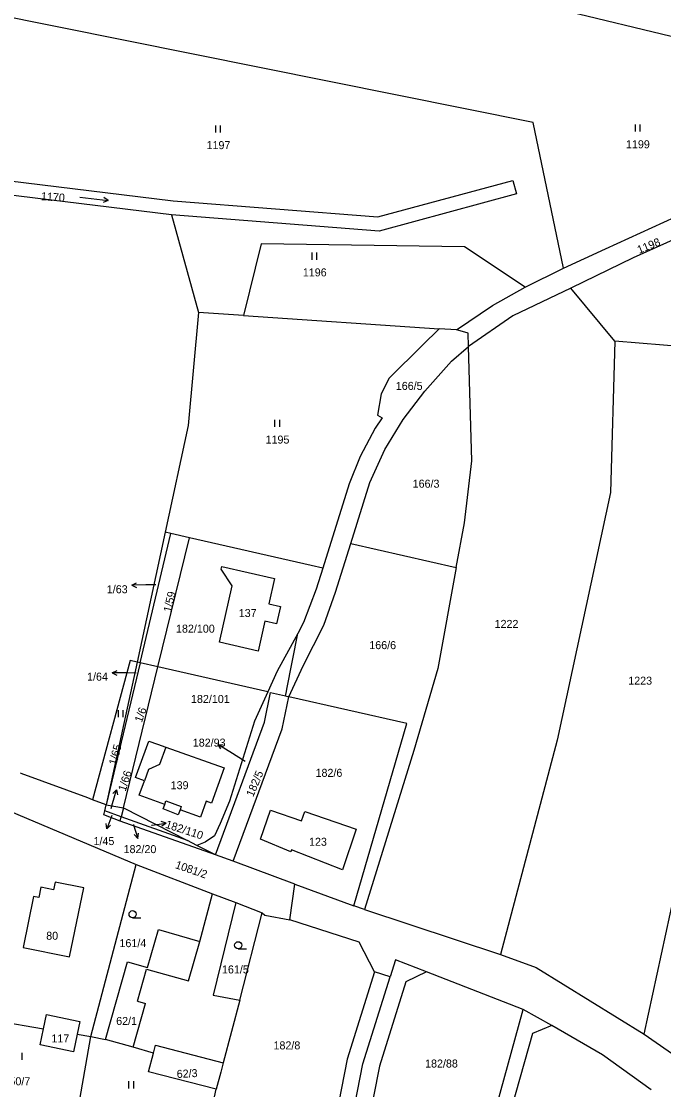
# Model space of a CAD drawing. Extents: x -746176 to -739709, y -1127410 to -1124482.
# Drawn here: x -742011.1 to -741874.7, y -1126433.2 to -1126206.3 of the extents above; entities that cross this region are included whole.
import ezdxf

# ---------------------------------------------------------------- set-up
doc = ezdxf.new("R2010")
doc.units = 0
for name, color, linetype in [('Hranice parcel', 7, 'Continuous'), ('Parcelní čísla', 7, 'Continuous'), ('Pop  PČ popisy', 7, 'Continuous'), ('Vnitřní kresba', 7, 'Continuous'), ('Značky kultur', 7, 'Continuous')]:
    doc.layers.add(name, color=color, linetype=linetype)

msp = doc.modelspace()

# ---------------------------------------------------------------- linework, layer by layer
at = {"layer": 'Hranice parcel'}
for p, q in [((-741979.16, -1126247.44), (-741973.49, -1126268.18)), ((-741904.1, -1126262.78), (-741895.95, -1126258.73)), ((-741885.09, -1126274.27), (-741894.45, -1126263.02)), ((-741963.91, -1126268.84), (-741973.49, -1126268.18)), ((-741963.91, -1126268.84), (-741922.39, -1126271.67)), ((-741918.69, -1126271.87), (-741922.39, -1126271.67)), ((-741856.86, -1126276.54), (-741885.09, -1126274.27)), ((-741980.55, -1126314.84), (-741986.51, -1126342.46)), ((-741985.86, -1126342.61), (-741979.32, -1126315.12)), ((-741982.09, -1126343.47), (-741975.4, -1126316.01)), ((-741979.32, -1126315.12), (-741980.55, -1126314.84)), ((-741975.4, -1126316.01), (-741979.32, -1126315.12)), ((-741941.15, -1126317.27), (-741918.74, -1126322.36)), ((-741951.16, -1126334.05), (-741952.39, -1126336.34)), ((-741952.39, -1126336.34), (-741956.73, -1126344.37)), ((-741986.51, -1126342.46), (-741993.03, -1126372.73)), ((-741985.86, -1126342.61), (-741993.03, -1126372.73)), ((-741989.38, -1126373.38), (-741982.09, -1126343.47)), ((-741985.86, -1126342.61), (-741986.51, -1126342.46)), ((-741982.09, -1126343.47), (-741985.86, -1126342.61)), ((-741958.73, -1126348.77), (-741982.09, -1126343.47)), ((-741954.27, -1126349.79), (-741951.24, -1126343.21)), ((-741956.73, -1126344.37), (-741958.73, -1126348.77)), ((-741955, -1126349.62), (-741954.27, -1126349.79)), ((-741993.03, -1126372.73), (-741995.94, -1126371.66)), ((-741993.33, -1126374), (-741993.03, -1126372.73)), ((-741993.03, -1126372.73), (-741989.38, -1126373.38)), ((-741989.85, -1126375.26), (-741993.33, -1126374)), ((-741990.09, -1126376.24), (-741989.85, -1126375.26)), ((-741989.38, -1126373.38), (-741989.85, -1126375.26)), ((-741975.79, -1126380.32), (-741989.85, -1126375.26)), ((-741989.38, -1126373.38), (-741975.79, -1126380.32)), ((-741969.88, -1126383.35), (-741990.09, -1126376.24)), ((-741973.78, -1126381.35), (-741975.79, -1126380.32)), ((-741972.03, -1126380.69), (-741973.78, -1126381.35)), ((-741969.88, -1126383.35), (-741973.78, -1126381.35)), ((-741966.13, -1126384.73), (-741969.88, -1126383.35)), ((-741996.32, -1126421.94), (-741986.71, -1126385.43)), ((-741986.71, -1126385.43), (-741970.45, -1126391.64)), ((-741953, -1126389.58), (-741966.13, -1126384.73)), ((-741954.07, -1126397.17), (-741953, -1126389.58)), ((-741953, -1126389.58), (-741940.51, -1126394.18)), ((-741970.45, -1126391.64), (-741965.53, -1126393.52)), ((-741965.53, -1126393.52), (-741959.96, -1126395.65)), ((-741964.66, -1126414.2), (-741959.96, -1126395.65)), ((-741938.23, -1126394.97), (-741940.51, -1126394.18)), ((-741938.23, -1126394.97), (-741909.32, -1126404.54)), ((-741932.77, -1126409.29), (-741936.11, -1126408.24)), ((-741904.57, -1126416.23), (-741925.07, -1126408.25)), ((-741964.66, -1126414.2), (-741968.2, -1126427.52)), ((-741898.42, -1126419.6), (-741904.57, -1126416.23)), ((-741999.2, -1126421.47), (-741996.32, -1126421.94)), ((-741999.11, -1126438.17), (-741996.32, -1126421.94)), ((-741996.32, -1126421.94), (-741993.21, -1126422.56)), ((-741878.88, -1126421.46), (-741852.49, -1126439.8)), ((-741971.96, -1126443.41), (-741969.67, -1126433.17))]:
    msp.add_line(p, q, dxfattribs=at)
for points in [[(-741895.95, -1126258.73), (-741902.39, -1126227.83), (-742032.39, -1126201.61)], [(-741748.2, -1126234.56), (-741750.5, -1126234.41), (-741798.02, -1126225.94), (-741818.62, -1126222.33), (-741833.76, -1126219.08), (-741900.7, -1126202.92)], [(-741979.16, -1126247.44), (-742018.02, -1126242.67), (-742051.56, -1126236.78), (-742071.8, -1126233.98)], [(-742037.23, -1126236.37), (-742017.58, -1126239.71), (-741978.86, -1126244.46), (-741935.37, -1126247.86), (-741906.75, -1126240.11), (-741905.97, -1126243.01), (-741935.09, -1126250.9), (-741979.16, -1126247.44)], [(-741895.95, -1126258.73), (-741887.06, -1126254.64), (-741867.23, -1126245.63), (-741859.7, -1126242.83), (-741853.68, -1126241.82), (-741840.1, -1126242.23)], [(-741841.74, -1126251.46), (-741852.27, -1126246.05), (-741856.49, -1126246.25), (-741862.01, -1126247.91), (-741881.16, -1126256.56), (-741894.45, -1126263.02)], [(-741904.1, -1126262.78), (-741917.02, -1126254.2), (-741960.14, -1126253.61), (-741963.91, -1126268.84)], [(-741918.69, -1126271.87), (-741911.03, -1126266.72), (-741904.1, -1126262.78)], [(-741894.45, -1126263.02), (-741906.75, -1126268.89), (-741916.15, -1126275.4)], [(-741973.49, -1126268.18), (-741975.66, -1126292.15), (-741980.55, -1126314.84)], [(-741922.39, -1126271.67), (-741925.91, -1126275.15), (-741932.95, -1126282.11), (-741934.69, -1126285.47), (-741935.47, -1126289.95), (-741934.45, -1126290.55), (-741935.93, -1126292.73), (-741939.16, -1126298.76), (-741941.48, -1126304.55), (-741947.05, -1126322.45)], [(-741916.15, -1126275.4), (-741916.23, -1126272.57), (-741918.37, -1126271.96), (-741918.69, -1126271.87)], [(-741941.15, -1126317.27), (-741937.11, -1126304.31), (-741933.93, -1126297.28), (-741929.99, -1126290.94), (-741925.39, -1126284.87), (-741919.74, -1126278.55), (-741916.15, -1126275.4)], [(-741918.74, -1126322.36), (-741917, -1126312.88), (-741915.44, -1126299.69), (-741916.15, -1126275.4)], [(-741885.09, -1126274.27), (-741886, -1126306.44), (-741897.34, -1126359), (-741909.32, -1126404.54)], [(-741878.88, -1126421.46), (-741868.71, -1126374.72), (-741857.4, -1126314.53), (-741856.86, -1126276.54)], [(-741947.05, -1126322.45), (-741949.55, -1126321.88), (-741975.4, -1126316.01)], [(-741951.24, -1126343.21), (-741946.82, -1126334.61), (-741944.36, -1126327.59), (-741941.15, -1126317.27)], [(-741969.03, -1126338.22), (-741966.34, -1126326.2), (-741968.61, -1126322.66), (-741968.49, -1126322.14), (-741957.3, -1126324.7), (-741958.52, -1126330.09), (-741956.07, -1126330.63), (-741956.89, -1126334.27), (-741959.34, -1126333.71), (-741960.77, -1126340.08), (-741969.03, -1126338.22)], [(-741947.05, -1126322.45), (-741948.46, -1126326.96), (-741951.16, -1126334.05)], [(-741918.74, -1126322.36), (-741922.66, -1126343.77), (-741927.73, -1126361.18), (-741938.23, -1126394.97)], [(-741955, -1126349.62), (-741954.81, -1126348.66), (-741954.71, -1126348.16), (-741952.39, -1126336.34)], [(-741986.51, -1126342.46), (-741987.96, -1126342.12), (-741995.94, -1126371.66)], [(-741958.73, -1126348.77), (-741961.57, -1126355.01), (-741966.88, -1126371.94), (-741968.84, -1126376.73), (-741970.09, -1126379.3), (-741972.03, -1126380.69)], [(-741969.88, -1126383.35), (-741959.42, -1126355.18), (-741958.17, -1126348.9), (-741955, -1126349.62)], [(-741966.13, -1126384.73), (-741955.67, -1126356.57), (-741954.27, -1126349.79)], [(-741940.51, -1126394.18), (-741929.25, -1126355.48), (-741954.27, -1126349.79)], [(-741977.77, -1126374.86), (-741980.95, -1126373.62), (-741980.61, -1126372.64), (-741986.02, -1126370.7), (-741984.92, -1126367.63), (-741986.82, -1126366.94), (-741984.02, -1126359.21), (-741982.15, -1126359.85), (-741980.39, -1126360.49), (-741968.02, -1126364.9), (-741970.7, -1126372.41), (-741971.84, -1126372), (-741973.03, -1126375.35), (-741977.37, -1126373.8), (-741977.77, -1126374.86)], [(-741995.94, -1126371.66), (-741996.93, -1126371.29), (-742011.08, -1126366.08), (-742011.25, -1126365.95)], [(-742017.65, -1126371.11), (-742017.02, -1126371.6), (-742014.99, -1126373.44), (-741986.71, -1126385.43)], [(-741990.09, -1126376.24), (-741993.53, -1126374.84), (-741993.33, -1126374)], [(-741958.18, -1126373.85), (-741951.58, -1126376.12), (-741950.91, -1126374.18), (-741939.97, -1126377.94), (-741942.91, -1126386.52), (-741953.71, -1126382.33), (-741953.86, -1126382.76), (-741960.32, -1126380.06), (-741958.18, -1126373.85)], [(-742003.87, -1126389.15), (-742004.21, -1126390.8), (-742006.94, -1126390.24), (-742007.38, -1126392.41), (-742008.47, -1126392.19), (-742010.7, -1126403.03), (-742000.83, -1126405.05), (-741997.82, -1126390.4), (-742003.87, -1126389.15)], [(-741993.21, -1126422.56), (-741988.52, -1126406.06), (-741984.26, -1126407.27), (-741981.98, -1126399.24), (-741973.18, -1126401.74), (-741970.45, -1126391.64)], [(-741965.53, -1126393.52), (-741970.31, -1126413.16), (-741964.66, -1126414.2)], [(-741959.96, -1126395.65), (-741959.39, -1126396.19), (-741954.07, -1126397.17)], [(-741936.11, -1126408.24), (-741939.36, -1126401.91), (-741954.07, -1126397.17)], [(-741909.32, -1126404.54), (-741901.76, -1126407.3), (-741878.88, -1126421.46)], [(-741925.07, -1126408.25), (-741931.64, -1126405.69), (-741932.77, -1126409.29)], [(-741954.32, -1126508.73), (-741938.56, -1126427.78), (-741932.77, -1126409.29)], [(-741936.11, -1126408.24), (-741941.9, -1126426.74), (-741946.15, -1126448.52)], [(-741925.07, -1126408.25), (-741929.41, -1126410.36), (-741935.06, -1126428.26), (-741937.58, -1126441.15)], [(-742024.68, -1126414.24), (-742015.91, -1126416.77), (-742016.26, -1126418.65), (-742006.36, -1126420.29)], [(-742006.36, -1126420.29), (-742005.72, -1126417.27), (-741998.63, -1126418.76), (-741999.2, -1126421.47)], [(-741912.45, -1126446.2), (-741911.72, -1126442.48), (-741904.57, -1126416.23)], [(-741999.2, -1126421.47), (-741999.99, -1126425.22), (-742007.08, -1126423.73), (-742006.36, -1126420.29)], [(-741898.42, -1126419.6), (-741902.57, -1126421.34), (-741908.84, -1126443.59), (-741914.46, -1126471.66), (-741921.58, -1126508.41), (-741929.05, -1126550.68), (-741935.86, -1126591.95), (-741938.82, -1126591.67)], [(-741877.38, -1126433.3), (-741887.7, -1126425.84), (-741898.42, -1126419.6)], [(-741983.01, -1126425.46), (-741987.35, -1126424.23), (-741993.21, -1126422.56)], [(-741983.01, -1126425.46), (-741982.58, -1126423.8), (-741968.2, -1126427.52)], [(-741969.67, -1126433.17), (-741984.04, -1126429.45), (-741983.01, -1126425.46)], [(-741968.2, -1126427.52), (-741968.72, -1126429.53), (-741969.67, -1126433.17)]]:
    msp.add_lwpolyline(points, dxfattribs=at)
at = {"layer": 'Pop  PČ popisy'}
for p, q in [((-741987.601, -1126326.082), (-741986.608, -1126325.564)), ((-741984.6, -1126326.03), (-741987.601, -1126326.082)), ((-741987.601, -1126326.082), (-741986.59, -1126326.566)), ((-741982.49, -1126326), (-741984.6, -1126326.03)), ((-741991.751, -1126344.678), (-741990.74, -1126344.194)), ((-741988.75, -1126344.73), (-741991.751, -1126344.678)), ((-741991.751, -1126344.678), (-741990.758, -1126345.196)), ((-741986.71, -1126344.75), (-741988.75, -1126344.73)), ((-741966.82, -1126361.51), (-741969.365, -1126359.92)), ((-741969.365, -1126359.92), (-741968.25, -1126360.026)), ((-741969.365, -1126359.92), (-741968.781, -1126360.875)), ((-741963.58, -1126363.54), (-741966.82, -1126361.51)), ((-741991.68, -1126372.43), (-741990.853, -1126369.545)), ((-741990.853, -1126369.545), (-741991.61, -1126370.37)), ((-741990.853, -1126369.545), (-741990.648, -1126370.646)), ((-741991.98, -1126373.5), (-741991.68, -1126372.43)), ((-741991.82, -1126375.03), (-741992.944, -1126377.812)), ((-741992.944, -1126377.812), (-741993.033, -1126376.696)), ((-741992.944, -1126377.812), (-741992.105, -1126377.072)), ((-741987.25, -1126376.89), (-741987.22, -1126377)), ((-741987.22, -1126377), (-741986.343, -1126379.87)), ((-741983.4, -1126377.04), (-741983.31, -1126377.03)), ((-741983.31, -1126377.03), (-741980.331, -1126376.664)), ((-741980.331, -1126376.664), (-741981.386, -1126376.289)), ((-741980.331, -1126376.664), (-741981.264, -1126377.283)), ((-741986.343, -1126379.87), (-741987.114, -1126379.059)), ((-741986.343, -1126379.87), (-741986.157, -1126378.766))]:
    msp.add_line(p, q, dxfattribs=at)
at = {"layer": 'Vnitřní kresba'}
for p, q in [((-741980.39, -1126360.49), (-741981.73, -1126364.15)), ((-741984.06, -1126365.24), (-741984.92, -1126367.63)), ((-741981.73, -1126364.15), (-741984.06, -1126365.24)), ((-741980.61, -1126372.64), (-741980.36, -1126371.92)), ((-741980.36, -1126371.92), (-741977.1, -1126373.07)), ((-741977.1, -1126373.07), (-741977.37, -1126373.8)), ((-741975.58, -1126410.16), (-741973.18, -1126401.74)), ((-741986.43, -1126414.45), (-741984.48, -1126407.62)), ((-741984.48, -1126407.62), (-741975.58, -1126410.16)), ((-741987.35, -1126424.23), (-741984.7, -1126414.94)), ((-741986.43, -1126414.45), (-741984.7, -1126414.94))]:
    msp.add_line(p, q, dxfattribs=at)
at = {"layer": 'Značky kultur'}
for p, q in [((-741969.751, -1126229.93), (-741969.751, -1126228.43)), ((-741968.75, -1126229.93), (-741968.75, -1126228.43)), ((-741880.711, -1126229.75), (-741880.711, -1126228.25)), ((-741879.71, -1126229.75), (-741879.71, -1126228.25)), ((-741998.622, -1126243.675), (-741992.666, -1126244.406)), ((-741992.666, -1126244.406), (-741993.697, -1126244.785)), ((-741992.666, -1126244.406), (-741993.575, -1126243.789)), ((-741949.311, -1126256.96), (-741949.311, -1126255.46)), ((-741948.31, -1126256.96), (-741948.31, -1126255.46)), ((-741957.221, -1126292.47), (-741957.221, -1126290.97)), ((-741956.22, -1126292.47), (-741956.22, -1126290.97)), ((-741990.471, -1126354.15), (-741990.471, -1126352.65)), ((-741989.47, -1126354.15), (-741989.47, -1126352.65)), ((-741987.453, -1126396.72), (-741985.703, -1126396.72)), ((-741965.033, -1126403.31), (-741963.283, -1126403.31)), ((-742010.86, -1126426.93), (-742010.86, -1126425.43)), ((-741988.211, -1126432.96), (-741988.211, -1126431.46)), ((-741987.21, -1126432.96), (-741987.21, -1126431.46))]:
    msp.add_line(p, q, dxfattribs=at)
for centre in [(-741987.453, -1126395.97), (-741965.033, -1126402.56)]:
    msp.add_circle(centre, 0.75, dxfattribs=at)

# ---------------------------------------------------------------- texts
at = {"layer": 'Parcelní čísla'}
for s, p in [('1197', (-741971.747, -1126233.48)), ('1199', (-741882.707, -1126233.3)), ('1196', (-741951.307, -1126260.51)), ('166/5', (-741931.573, -1126284.62)), ('1195', (-741959.217, -1126296.02)), ('166/3', (-741927.993, -1126305.39)), ('1/63', (-741992.921, -1126327.81)), ('137', (-741964.914, -1126332.86)), ('182/100', (-741978.228, -1126336.18)), ('1222', (-741910.597, -1126335.17)), ('166/6', (-741937.203, -1126339.68)), ('1/64', (-741997.111, -1126346.37)), ('1223', (-741882.227, -1126347.23)), ('182/101', (-741975.048, -1126351.11)), ('182/93', (-741974.665, -1126360.38)), ('182/6', (-741948.61, -1126366.8)), ('139', (-741979.364, -1126369.43)), ('1/45', (-741995.741, -1126381.293)), ('123', (-741949.994, -1126381.44)), ('182/20', (-741989.355, -1126383.003)), ('80', (-742005.782, -1126401.4)), ('161/4', (-741990.233, -1126402.97)), ('161/5', (-741968.473, -1126408.56)), ('62/1', (-741990.931, -1126419.5)), ('117', (-742004.674, -1126423.21)), ('182/8', (-741957.53, -1126424.69)), ('182/88', (-741925.355, -1126428.54)), ('150/7', (-742014.853, -1126432.31))]:
    msp.add_text(s, height=1.7, dxfattribs=at).set_placement(p)
for s, rotation, p in [('1170', 356, (-742006.94, -1126244.313)), ('1198', 22, (-741879.916, -1126255.727)), ('1/59', 77, (-741979.275, -1126331.964)), ('1/6', 70, (-741985.501, -1126355.38)), ('1/65', 75, (-741990.898, -1126364.434)), ('1/66', 72, (-741988.954, -1126370.014)), ('182/5', 67, (-741961.847, -1126371.182)), ('182/110', 342, (-741980.612, -1126377.582)), ('1081/2', 341, (-741978.536, -1126386.163)), ('62/3', 3, (-741978.033, -1126430.776))]:
    msp.add_text(s, height=1.7, rotation=rotation, dxfattribs=at).set_placement(p)

doc.saveas('drawing.dxf')
